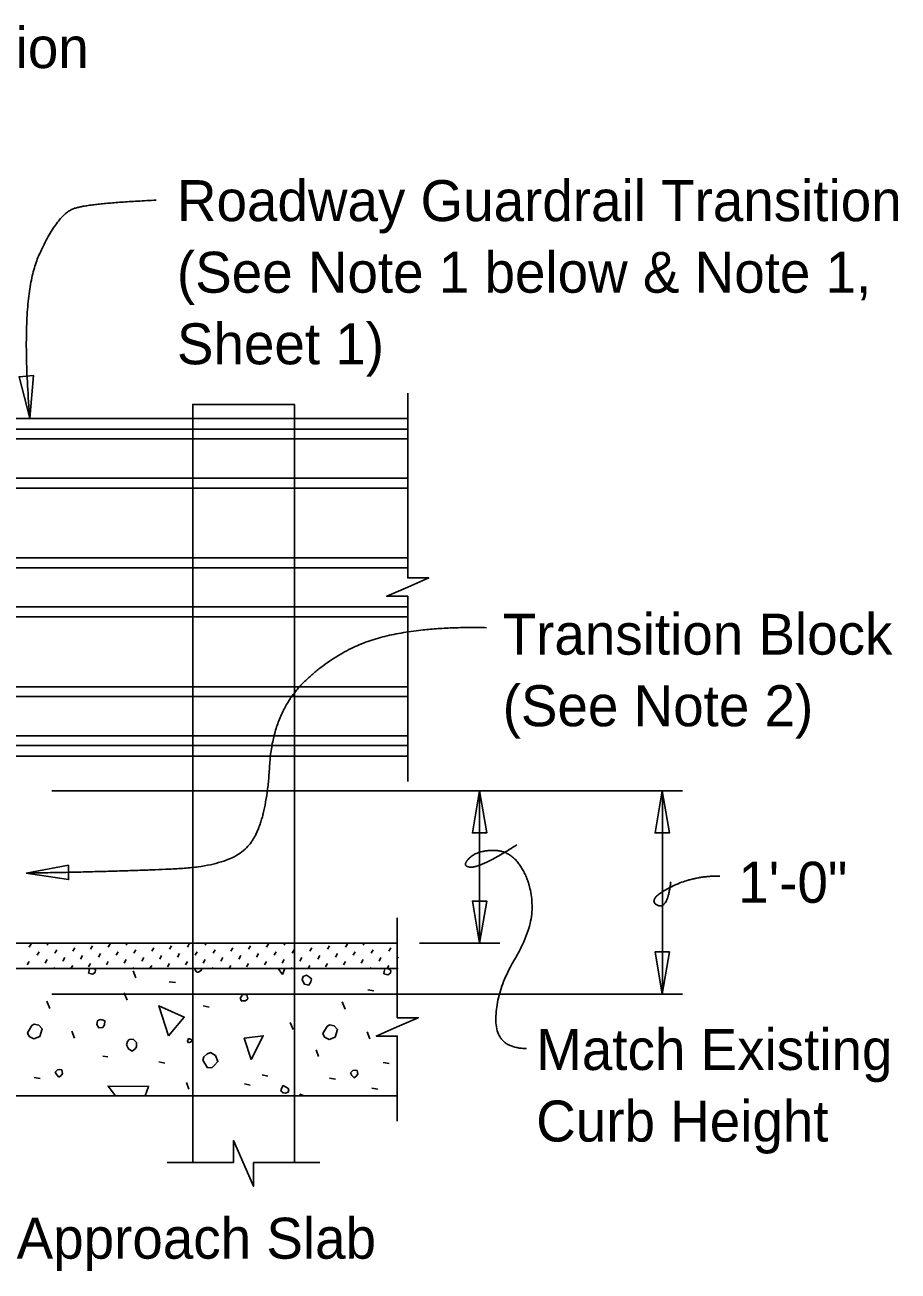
# Model space of a CAD drawing. Extents: x 1 to 39.2, y 0 to 26.
# Drawn here: x 33.07 to 37.37, y 9.27 to 15.4 of the extents above; entities that cross this region are included whole.
import ezdxf

# ---------------------------------------------------------------- set-up
doc = ezdxf.new("R2010")
doc.units = 0
for name, color, linetype in [('Dimension', 7, 'Continuous'), ('Miscellaneous', 7, 'Continuous'), ('TextStructures', 7, 'Continuous'), ('TrafBarrierConc', 7, 'Continuous')]:
    doc.layers.add(name, color=color, linetype=linetype)

# ---------------------------------------------------------------- blocks, each defined once
blk = doc.blocks.new('Terminator-Arrow')
at = {"layer": 'Dimension'}
blk.add_lwpolyline([(0, 0), (-0.00041, 0.000069), (-0.00041, -0.000069)], close=True, dxfattribs=at)

msp = doc.modelspace()

# ---------------------------------------------------------------- linework, layer by layer
at = {"layer": 'Dimension'}
for p, q in [((33.2046, 11.633), (36.3081, 11.633)), ((35.3092, 11.6331), (35.3092, 10.883)), ((36.2084, 11.6331), (36.2084, 10.6331)), ((35.0141, 10.883), (35.4089, 10.883)), ((33.2046, 10.633), (36.3081, 10.633))]:
    msp.add_line(p, q, dxfattribs=at)
for points in [[(33.0961, 13.4646), (33.1136, 13.6751), (33.0433, 13.6691)], [(33.0779, 11.2279), (33.2867, 11.1961), (33.2855, 11.2666)]]:
    msp.add_lwpolyline(points, close=True, dxfattribs=at)
for points in [[(34.9557, 11.6779), (34.9557, 12.5891), (34.8524, 12.5891), (34.9557, 12.6341), (35.059, 12.6791), (34.9557, 12.6791), (34.9557, 13.588)], [(34.904, 10.008), (34.904, 10.4262), (34.8006, 10.4262), (34.904, 10.4712), (35.0073, 10.5162), (34.904, 10.5162), (34.904, 11.008)], [(34.5225, 9.8041), (34.1972, 9.8041), (34.1972, 9.6878), (34.0978, 9.9128), (34.0978, 9.8041), (33.7725, 9.8041)]]:
    msp.add_lwpolyline(points, dxfattribs=at)
for points in [[(33.7178, 14.537), (33.4034, 14.5227), (33.2319, 14.4727), (33.0461, 14.0509), (33.0961, 13.4646)], [(35.3436, 12.4347), (35.0439, 12.4415), (34.6327, 12.3403), (34.2903, 12.0261), (34.2603, 11.4744), (34.0947, 11.263), (33.5472, 11.2357), (33.0778, 11.2278)], [(35.5399, 10.3654), (35.3892, 10.3654), (35.3892, 10.6467), (35.5674, 10.9485), (35.5674, 11.168), (35.4645, 11.3395), (35.2932, 11.3395), (35.2178, 11.2572), (35.3206, 11.2572), (35.492, 11.367)], [(36.2498, 11.1856), (36.2338, 11.0442), (36.1325, 11.0961), (36.3498, 11.2135), (36.4912, 11.2135)]]:
    msp.add_open_spline(points, degree=2, dxfattribs=at)
at = {"layer": 'Miscellaneous'}
for p, q in [((27.784, 13.463), (34.9557, 13.463)), ((28.4416, 13.4108), (34.9557, 13.4108)), ((28.4429, 13.3626), (34.9557, 13.3626)), ((28.4476, 13.1698), (34.9557, 13.1698)), ((28.4487, 13.1215), (34.9557, 13.1215)), ((28.4453, 12.7776), (34.9557, 12.7776)), ((28.444, 12.7293), (34.9557, 12.7293)), ((28.4388, 12.5365), (34.9557, 12.5365)), ((28.4346, 12.4884), (34.9557, 12.4884)), ((28.4487, 12.1444), (34.9557, 12.1444)), ((28.4476, 12.0962), (34.9557, 12.0962)), ((28.4413, 11.9034), (34.9557, 11.9034)), ((28.4423, 11.8552), (34.9557, 11.8552)), ((27.784, 11.8029), (34.9557, 11.8029)), ((33.0932, 10.8635), (33.1029, 10.8803)), ((33.1807, 10.8732), (33.1863, 10.883)), ((33.2196, 10.8344), (33.2293, 10.8511)), ((33.3071, 10.8441), (33.3168, 10.8609)), ((33.3946, 10.8538), (33.4043, 10.8706)), ((33.4821, 10.8635), (33.4918, 10.8803)), ((33.5696, 10.8732), (33.5752, 10.883)), ((33.6085, 10.8344), (33.6182, 10.8511)), ((33.696, 10.8441), (33.7057, 10.8609)), ((33.7835, 10.8538), (33.7932, 10.8706)), ((33.871, 10.8635), (33.8807, 10.8803)), ((33.9585, 10.8732), (33.9641, 10.883)), ((33.9974, 10.8344), (34.0071, 10.8511)), ((34.0849, 10.8441), (34.0946, 10.8609)), ((34.1724, 10.8538), (34.1821, 10.8706)), ((34.2599, 10.8635), (34.2696, 10.8803)), ((34.3474, 10.8732), (34.353, 10.883)), ((34.3863, 10.8344), (34.396, 10.8511)), ((34.4738, 10.8441), (34.4835, 10.8609)), ((34.5613, 10.8538), (34.571, 10.8706)), ((34.6488, 10.8635), (34.6585, 10.8803)), ((34.7363, 10.8732), (34.7419, 10.883)), ((34.7752, 10.8344), (34.7849, 10.8511)), ((34.8627, 10.8441), (34.8724, 10.8609)), ((33.0834, 10.776), (33.0932, 10.7928)), ((33.1321, 10.8246), (33.1418, 10.8414)), ((33.1709, 10.7857), (33.1807, 10.8025)), ((33.2585, 10.7955), (33.2682, 10.8123)), ((33.346, 10.8052), (33.3557, 10.822)), ((33.4335, 10.8149), (33.4432, 10.8317)), ((33.4724, 10.776), (33.4821, 10.7928)), ((33.521, 10.8246), (33.5307, 10.8414)), ((33.5599, 10.7857), (33.5696, 10.8025)), ((33.6474, 10.7955), (33.6571, 10.8123)), ((33.7349, 10.8052), (33.7446, 10.822)), ((33.8224, 10.8149), (33.8321, 10.8317)), ((33.8613, 10.776), (33.871, 10.7928)), ((33.9099, 10.8246), (33.9196, 10.8414)), ((33.9488, 10.7857), (33.9585, 10.8025)), ((34.0363, 10.7955), (34.046, 10.8123)), ((34.1238, 10.8052), (34.1335, 10.822)), ((34.2113, 10.8149), (34.221, 10.8317)), ((34.2502, 10.776), (34.2599, 10.7928)), ((34.2988, 10.8246), (34.3085, 10.8414)), ((34.3377, 10.7857), (34.3474, 10.8025)), ((34.4252, 10.7955), (34.4349, 10.8123)), ((34.5127, 10.8052), (34.5224, 10.822)), ((34.6002, 10.8149), (34.6099, 10.8317)), ((34.6391, 10.776), (34.6488, 10.7928)), ((34.6877, 10.8246), (34.6974, 10.8414)), ((34.7266, 10.7857), (34.7363, 10.8025)), ((34.8141, 10.7955), (34.8238, 10.8123)), ((34.9016, 10.8052), (34.9076, 10.8155)), ((33.2163, 10.758), (33.2196, 10.7636)), ((33.2982, 10.758), (33.3071, 10.7734)), ((33.3848, 10.7663), (33.3946, 10.7831)), ((33.617, 10.7128), (33.6046, 10.7464)), ((33.6052, 10.758), (33.6085, 10.7636)), ((33.6871, 10.758), (33.696, 10.7734)), ((33.7738, 10.7663), (33.7835, 10.7831)), ((33.9941, 10.758), (33.9974, 10.7636)), ((34.076, 10.758), (34.0849, 10.7734)), ((34.1627, 10.7663), (34.1724, 10.7831)), ((34.383, 10.758), (34.3863, 10.7636)), ((34.4649, 10.758), (34.4738, 10.7734)), ((34.5516, 10.7663), (34.5613, 10.7831)), ((34.7719, 10.758), (34.7752, 10.7636)), ((34.8538, 10.758), (34.8627, 10.7734)), ((33.7814, 10.6934), (33.8132, 10.6898)), ((33.5746, 10.6032), (33.5604, 10.6386)), ((34.7592, 10.6534), (34.7892, 10.6481)), ((33.1945, 10.5625), (33.1804, 10.5979)), ((33.9493, 10.5749), (33.9776, 10.5678)), ((34.6476, 10.559), (34.6335, 10.5944)), ((34.3913, 10.4582), (34.3771, 10.4936)), ((33.3165, 10.4158), (33.3023, 10.4512)), ((34.7696, 10.4123), (34.7554, 10.4476)), ((34.5168, 10.3257), (34.5044, 10.3592)), ((33.4544, 10.3274), (33.4791, 10.3239)), ((33.7301, 10.2991), (33.7602, 10.2938)), ((34.8346, 10.2962), (34.8646, 10.2909)), ((34.2392, 10.2355), (34.2675, 10.2284)), ((33.1167, 10.2231), (33.1468, 10.2178)), ((33.8786, 10.1648), (33.8662, 10.1984)), ((34.1526, 10.1913), (34.1809, 10.1842)), ((34.5698, 10.2196), (34.5999, 10.2143)), ((34.7784, 10.1701), (34.8084, 10.1648))]:
    msp.add_line(p, q, dxfattribs=at)
for points in [[(34.3975, 9.8041), (34.3975, 13.5329), (33.8975, 13.5329), (33.8975, 9.8041)], [(33.3854, 10.7358), (33.4049, 10.7305), (33.4172, 10.7393), (33.419, 10.7517), (33.4155, 10.7552), (33.41, 10.758)], [(33.3886, 10.758), (33.3872, 10.7482), (33.3854, 10.7358)], [(33.9072, 10.758), (33.9104, 10.7482), (33.9175, 10.7411)], [(33.9175, 10.7411), (33.9246, 10.7411), (33.9387, 10.7482), (33.942, 10.758)], [(34.34, 10.7287), (34.3178, 10.758)], [(34.3509, 10.758), (34.34, 10.7287)], [(34.439, 10.6969), (34.4478, 10.681), (34.4691, 10.6774), (34.4779, 10.6934), (34.4814, 10.7075), (34.4726, 10.7163), (34.4567, 10.7252), (34.4408, 10.7199), (34.4355, 10.704), (34.439, 10.6969)], [(34.8385, 10.7322), (34.858, 10.7269), (34.8703, 10.7358), (34.8721, 10.7482), (34.8686, 10.7517), (34.856, 10.758)], [(34.8489, 10.758), (34.8421, 10.757), (34.8403, 10.7446), (34.8385, 10.7322)], [(34.1367, 10.5997), (34.1579, 10.5997), (34.1685, 10.6103), (34.1632, 10.6297), (34.1403, 10.6315), (34.1367, 10.6209), (34.1314, 10.612), (34.1367, 10.5997), (34.1332, 10.6032)], [(33.7779, 10.4282), (33.7301, 10.5749), (33.8556, 10.5201), (33.7779, 10.4282)], [(33.092, 10.4247), (33.1149, 10.4123), (33.145, 10.4247), (33.1574, 10.4618), (33.1397, 10.4795), (33.1167, 10.4848), (33.1061, 10.4777), (33.0937, 10.4582), (33.0849, 10.4423), (33.092, 10.4247)], [(33.4261, 10.483), (33.4349, 10.4671), (33.4544, 10.4688), (33.4632, 10.4812), (33.465, 10.5007), (33.4526, 10.506), (33.4438, 10.5077), (33.4331, 10.5042), (33.4296, 10.5007), (33.4261, 10.483)], [(34.5451, 10.4211), (34.5681, 10.4087), (34.5981, 10.4211), (34.6105, 10.4582), (34.5928, 10.4759), (34.5698, 10.4812), (34.5592, 10.4742), (34.5468, 10.4547), (34.538, 10.4388), (34.5451, 10.4211)], [(34.1844, 10.3115), (34.1509, 10.4158), (34.2446, 10.4282), (34.1844, 10.3115)], [(33.571, 10.384), (33.5816, 10.3628), (33.5993, 10.3522), (33.6135, 10.3628), (33.6205, 10.3734), (33.6205, 10.3946), (33.6046, 10.4105), (33.5852, 10.4087), (33.5763, 10.3999), (33.571, 10.384)], [(33.8769, 10.3928), (33.8963, 10.4017), (33.8892, 10.4087), (33.8769, 10.414), (33.8716, 10.4017), (33.8769, 10.3928)], [(33.9476, 10.308), (33.9705, 10.2709), (33.9935, 10.2726), (34.0024, 10.2815), (34.0218, 10.3009), (34.0094, 10.331), (33.9847, 10.3451), (33.967, 10.338), (33.9529, 10.3239), (33.9476, 10.308)], [(33.2281, 10.2355), (33.2387, 10.2249), (33.2493, 10.232), (33.2564, 10.2426), (33.2528, 10.2603), (33.244, 10.262), (33.2316, 10.2603), (33.221, 10.2496), (33.2281, 10.2355)], [(34.6812, 10.232), (34.6918, 10.2214), (34.7024, 10.2284), (34.7095, 10.239), (34.7059, 10.2567), (34.6971, 10.2585), (34.6847, 10.2567), (34.6741, 10.2461), (34.6812, 10.232)], [(33.5171, 10.133), (33.4809, 10.1807), (33.6806, 10.1789), (33.6635, 10.133)], [(34.3418, 10.1471), (34.3542, 10.1453), (34.3665, 10.1506), (34.3701, 10.1613), (34.3648, 10.1701), (34.3542, 10.1772), (34.3418, 10.1825), (34.3347, 10.1683), (34.3312, 10.1577), (34.3418, 10.1471)], [(34.4245, 10.133), (34.4266, 10.14), (34.4445, 10.133)]]:
    msp.add_lwpolyline(points, dxfattribs=at)
at = {"layer": 'TrafBarrierConc'}
for p, q in [((29.7751, 10.883), (34.904, 10.883)), ((29.7751, 10.758), (34.9091, 10.758)), ((27.0656, 10.133), (34.904, 10.133))]:
    msp.add_line(p, q, dxfattribs=at)

# ---------------------------------------------------------------- block references
at = {"layer": 'Dimension', "xscale": 506.349, "yscale": -512.1577380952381}
for p, rotation in [((35.3087, 11.6329), 90), ((36.2079, 11.6329), 90), ((35.309, 10.8828), -90), ((36.2079, 10.6328), -90)]:
    msp.add_blockref('Terminator-Arrow', p, dxfattribs=dict(at, rotation=rotation))

# ---------------------------------------------------------------- texts
at = {"layer": 'Dimension'}
for s, p in [('Railing End Transition ', (30.7487, 15.1866)), ('Roadway Guardrail Transition', (33.8198, 14.4339)), ('(See Note 1 below & Note 1, ', (33.8198, 14.0819)), ('Sheet 1)', (33.8198, 13.7299)), ('Transition Block', (35.4226, 12.302)), ('(See Note 2)', (35.4226, 11.95)), ('Match Existing ', (35.5877, 10.2596)), ('Curb Height', (35.5877, 9.9076))]:
    msp.add_text(s, height=0.2016, dxfattribs=at).set_placement(p)
at = {"layer": 'TextStructures'}
for s, p in [('1\'-0"', (36.582, 11.0819)), ('Existing Approach Slab', (32.0121, 9.3315))]:
    msp.add_text(s, height=0.2016, dxfattribs=at).set_placement(p)

doc.saveas('drawing.dxf')
